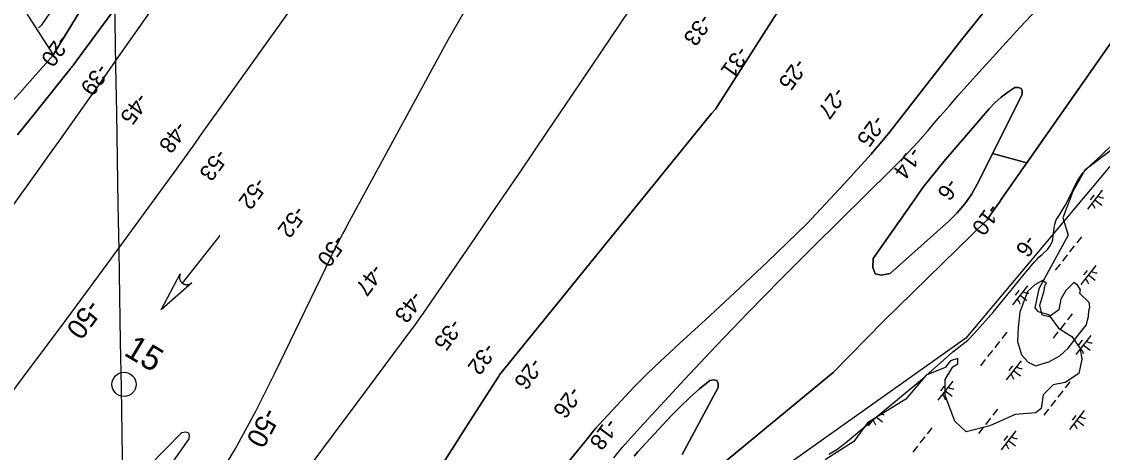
# Model space of a CAD drawing. Extents: x 3896831 to 3918110, y 171006 to 193349.
# Drawn here: x 3904219 to 3906456, y 175459 to 176349 of the extents above; entities that cross this region are included whole.
import ezdxf

# ---------------------------------------------------------------- set-up
doc = ezdxf.new("R2010")
doc.units = 0
for name, color, linetype in [('V-GRID-MAJR', 7, 'Continuous'), ('V-RIVR-EDGE', 7, 'Continuous'), ('V-RIVR-IDEN', 7, 'Continuous'), ('V-RIVR-MILE', 7, 'Continuous'), ('V-RIVR-RANG', 7, 'Continuous'), ('V-RRAP-FSHR', 7, 'Continuous'), ('V-STRM-FLOW', 7, 'Continuous'), ('V-TOPO-DPTH', 7, 'Continuous'), ('V-TOPO-MAJR', 7, 'Continuous'), ('V-TOPO-MAJR-IDEN', 7, 'Continuous'), ('V-TOPO-MINR', 7, 'Continuous'), ('V-TOPO-SHOR', 7, 'Continuous'), ('V-WETL-SWMP', 7, 'Continuous')]:
    doc.layers.add(name, color=color, linetype=linetype)

msp = doc.modelspace()

# ---------------------------------------------------------------- linework, layer by layer
at = {"layer": 'V-GRID-MAJR'}
msp.add_spline([(3904462.5, 173418.2), (3904435.1, 175024.2), (3904332, 181084.3), (3904281.2, 184068.5)], degree=3, dxfattribs=at)
at = {"layer": 'V-RIVR-EDGE'}
msp.add_lwpolyline([(3906485.3, 176092), (3906419.6, 176042), (3906394.6, 175998.2), (3906374.3, 175943.5), (3906385.3, 175907.6), (3906324.3, 175796.6), (3906316.5, 175757.5), (3906322.7, 175749.7), (3906344.6, 175743.5), (3906364.9, 175715.3), (3906393.1, 175698.1), (3906410.3, 175673.1), (3906413.4, 175651.2), (3906407.1, 175621.5), (3906379, 175602.8), (3906354, 175598.1), (3906333.7, 175577.8), (3906329, 175549.6), (3906318, 175540.3), (3906275.8, 175537.1), (3906222.7, 175513.7), (3906174.2, 175501.2), (3906150.8, 175523.1), (3906130.5, 175576.2), (3906130.5, 175609), (3906146.1, 175635.6), (3906157, 175641.9), (3906157, 175652.8), (3906141.4, 175648.1), (3906130.5, 175634), (3906091.4, 175618.4), (3906049.2, 175568.4), (3905969.5, 175519.9), (3905941.3, 175480.9), (3905881.9, 175443.3)], dxfattribs=at)
at = {"layer": 'V-RIVR-MILE'}
msp.add_circle((3904430.9, 175599.1), 25, dxfattribs=at)
at = {"layer": 'V-RRAP-FSHR'}
msp.add_lwpolyline([(3908001.4, 176472.2), (3907201.3, 176920.5), (3906173.6, 175695), (3905294, 175071.7), (3904787.4, 174237.7)], dxfattribs=at)
at = {"layer": 'V-STRM-FLOW'}
msp.add_line((3904629.1, 175906.9), (3904551.5, 175808.6), dxfattribs=at)
msp.add_lwpolyline([(3904571, 175809.1), (3904507.6, 175753), (3904547.4, 175827.7), (3904546.8, 175826.3), (3904546.3, 175824.9), (3904546.2, 175824.4), (3904546, 175823.9), (3904545.9, 175823.2), (3904545.8, 175822.6), (3904545.8, 175822.1), (3904545.7, 175821.4), (3904545.7, 175820.6), (3904545.7, 175820.2), (3904545.7, 175819.6), (3904545.8, 175818.9), (3904545.8, 175818.3), (3904545.9, 175817.7), (3904546, 175817.3), (3904546.1, 175816.9), (3904546.3, 175816.4), (3904546.4, 175815.9), (3904546.6, 175815.4), (3904546.7, 175815), (3904547, 175814.5), (3904547.2, 175813.9), (3904547.4, 175813.5), (3904547.7, 175813), (3904547.9, 175812.6), (3904548.1, 175812.3), (3904548.3, 175812), (3904548.6, 175811.6), (3904548.9, 175811.2), (3904549.2, 175810.8), (3904549.6, 175810.4), (3904549.9, 175810.1), (3904550.2, 175809.7), (3904550.5, 175809.4), (3904551, 175809), (3904551.5, 175808.6), (3904551.6, 175808.5), (3904551.9, 175808.3), (3904552.2, 175808.1), (3904552.5, 175807.9), (3904552.8, 175807.7), (3904553.1, 175807.5), (3904553.4, 175807.3), (3904553.6, 175807.2), (3904554, 175807), (3904554.3, 175806.8), (3904554.6, 175806.7), (3904555.2, 175806.4), (3904555.5, 175806.3), (3904555.8, 175806.2), (3904556.1, 175806.1), (3904556.5, 175806), (3904556.9, 175805.9), (3904557.3, 175805.8), (3904557.7, 175805.7), (3904558, 175805.6), (3904558.3, 175805.5), (3904558.7, 175805.5), (3904559, 175805.4), (3904559.4, 175805.4), (3904559.8, 175805.4), (3904560.2, 175805.3), (3904560.7, 175805.3), (3904561.1, 175805.3), (3904561.5, 175805.3), (3904561.9, 175805.4), (3904562.2, 175805.4), (3904562.6, 175805.4), (3904563.1, 175805.5), (3904563.1, 175805.5), (3904563.4, 175805.5), (3904563.7, 175805.6), (3904564, 175805.6), (3904564.4, 175805.7), (3904564.7, 175805.8), (3904565, 175805.9), (3904565.4, 175806), (3904565.8, 175806.1), (3904566, 175806.2), (3904566.4, 175806.3), (3904566.8, 175806.5), (3904567.1, 175806.6), (3904567.3, 175806.7), (3904567.5, 175806.8), (3904567.7, 175806.9), (3904568, 175807.1), (3904568.3, 175807.2), (3904568.6, 175807.4), (3904568.8, 175807.5), (3904569.2, 175807.8), (3904569.4, 175807.9), (3904569.7, 175808.1), (3904570.1, 175808.4), (3904570.4, 175808.6), (3904570.6, 175808.8), (3904570.8, 175808.9), (3904570.9, 175809)], close=True, dxfattribs=at)
at = {"layer": 'V-TOPO-DPTH'}
for points in [[(3904799.7, 176900.9), (3904331.9, 176267.3), (3904330.3, 176265.2), (3904328.6, 176263), (3904327, 176260.9), (3904325.3, 176258.7), (3904323.7, 176256.6), (3904322, 176254.4), (3904320.3, 176252.3), (3904318.6, 176250.2), (3904247.5, 176161.7), (3904210.5, 176115.2)], [(3904210.5, 176115.2), (3904247.5, 176161.7), (3904318.6, 176250.2), (3904320.3, 176252.3), (3904322, 176254.4), (3904323.7, 176256.6), (3904325.3, 176258.7), (3904327, 176260.9), (3904328.6, 176263), (3904330.3, 176265.2), (3904331.9, 176267.3), (3904799.7, 176900.9)], [(3904426.4, 174510.2), (3904808.6, 174976.7), (3904809.5, 174976.7), (3904811.1, 174977.5), (3904811.8, 174978.3), (3905022.7, 175325.1), (3905053.3, 175375), (3905084.1, 175424.7), (3905115.4, 175474.1), (3905147, 175523.4), (3905207, 175616.4), (3905208.1, 175619.1), (3905647, 176159.4), (3905655.1, 176168.1), (3905914, 176573.8), (3905940.5, 176609.6), (3905968.3, 176644.2), (3905998, 176677.2), (3906029, 176709.2), (3906062.2, 176738.6), (3906096.9, 176765.8), (3906134, 176789.7), (3906172.7, 176811.4), (3906272.9, 176861.8)], [(3906272.9, 176861.8), (3906172.7, 176811.4), (3906134, 176789.7), (3906096.9, 176765.8), (3906062.2, 176738.6), (3906029, 176709.2), (3905998, 176677.2), (3905968.3, 176644.2), (3905940.5, 176609.6), (3905914, 176573.8), (3905655.1, 176168.1), (3905647, 176159.4), (3905208.1, 175619.1), (3905207, 175616.4), (3905147, 175523.4), (3905115.4, 175474.1), (3905084.1, 175424.7), (3905053.3, 175375), (3905022.7, 175325.1), (3904811.8, 174978.3), (3904811.1, 174977.5), (3904809.5, 174976.7), (3904808.6, 174976.7), (3904426.4, 174510.2)], [(3906657.1, 176567.6), (3906656.4, 176566.7), (3906299.5, 176057)], [(3903989.7, 175948.1), (3904284.6, 176280.7), (3904284.8, 176281), (3904284.9, 176281.2), (3904423.5, 176509)], [(3904423.5, 176509), (3904284.9, 176281.2), (3904284.8, 176281), (3904284.6, 176280.7)], [(3904820.2, 175436.4), (3904864.8, 175495.8), (3904909.2, 175555.2), (3904953.6, 175614.6), (3905023.5, 175708.5), (3905032.8, 175721.1), (3905042, 175733.8), (3905051, 175746.6), (3905059.9, 175759.5), (3905148, 175888), (3905200.8, 175965.2), (3905253.5, 176042.5), (3905306, 176120), (3905358.5, 176197.5), (3905477, 176373.3)], [(3904820.2, 175436.4), (3904864.8, 175495.8), (3904909.2, 175555.2), (3904953.6, 175614.6), (3905023.5, 175708.5), (3905032.8, 175721.1), (3905042, 175733.8), (3905051, 175746.6), (3905059.9, 175759.5), (3905148, 175888), (3905200.8, 175965.2), (3905253.5, 176042.5), (3905306, 176120), (3905358.5, 176197.5), (3905477, 176373.3)], [(3905302.6, 175379.7), (3905393.4, 175491.5), (3905400.5, 175500.1), (3905407.7, 175508.5), (3905415, 175516.8), (3905422.5, 175525.1), (3905459.9, 175565.4), (3905486.4, 175593.3), (3905513.5, 175620.8), (3905541.3, 175647.5), (3905569.6, 175673.7), (3905573.4, 175677.1), (3905603.9, 175704.8), (3905634.2, 175732.5), (3905664.4, 175760.4), (3905694.5, 175788.5), (3905762.9, 175852.5), (3905803.7, 175891.7), (3905843.9, 175931.5), (3905883, 175972.3), (3905921.4, 176013.8), (3905977.3, 176075.5), (3905987.2, 176086.7), (3905997, 176098), (3906006.5, 176109.6), (3906015.8, 176121.3), (3906164.7, 176311.6), (3906218.2, 176378.2)], [(3906218.2, 176378.2), (3906164.7, 176311.6), (3906015.8, 176121.3), (3906006.5, 176109.6), (3905997, 176098), (3905987.2, 176086.7), (3905977.3, 176075.5), (3905921.4, 176013.8), (3905883, 175972.3), (3905843.9, 175931.5), (3905803.7, 175891.7), (3905762.9, 175852.5), (3905694.5, 175788.5), (3905664.4, 175760.4), (3905634.2, 175732.5), (3905603.9, 175704.8), (3905573.4, 175677.1), (3905569.6, 175673.7), (3905541.3, 175647.5), (3905513.5, 175620.8), (3905486.4, 175593.3), (3905459.9, 175565.4), (3905422.5, 175525.1), (3905415, 175516.8), (3905407.7, 175508.5), (3905400.5, 175500.1), (3905393.4, 175491.5), (3905302.6, 175379.7)], [(3904483.2, 176367.5), (3904461.6, 176337.2), (3904440.2, 176306.8), (3904418.9, 176276.2), (3904383.2, 176225), (3904379.8, 176220.1), (3904376.3, 176215.2), (3904372.8, 176210.2), (3904369.4, 176205.3), (3904336.2, 176158.8), (3904316.1, 176130.6), (3904296, 176102.4), (3904275.8, 176074.3), (3904255.6, 176046.2), (3903945, 175614.1)], [(3904483.2, 176367.5), (3904461.6, 176337.2), (3904440.2, 176306.8), (3904418.9, 176276.2), (3904383.2, 176225), (3904379.8, 176220.1), (3904376.3, 176215.2), (3904372.8, 176210.2), (3904369.4, 176205.3), (3904336.2, 176158.8), (3904316.1, 176130.6), (3904296, 176102.4), (3904275.8, 176074.3), (3904255.6, 176046.2), (3903945, 175614.1)], [(3904284.6, 176280.7), (3904227.6, 176369.7)], [(3906299.5, 176057), (3906228.7, 176076.6), (3906289.8, 176198.7), (3906289.8, 176206.1), (3906287.6, 176211.2), (3906282.4, 176213.1), (3906275, 176212.8), (3906260.3, 176203.3), (3906246.4, 176193), (3906233.6, 176181.3), (3906221.5, 176168.7), (3906127.9, 176060.3), (3906113, 176042.5), (3906098.5, 176024.5)], [(3906098.5, 176024.5), (3906084.6, 176006), (3906071.1, 175987.2), (3905981.8, 175859.3), (3905980.8, 175840.6), (3905985.5, 175828.1), (3905998.4, 175825), (3906016.9, 175828.2), (3906138.3, 175936.7), (3906155.5, 175953.9), (3906171.3, 175972.2), (3906184.8, 175992.1), (3906196.9, 176013.2), (3906224.8, 176069), (3906228.7, 176076.6), (3906299.5, 176057), (3906289.4, 176042.6)], [(3906289.4, 176042.6), (3906247.9, 175983.4), (3906242.8, 175976), (3906237.6, 175968.6), (3906232.4, 175961.2), (3906227.3, 175953.8), (3906217.5, 175939.7), (3906216.3, 175938.3), (3906003.2, 175730), (3905898.6, 175623.6), (3905669.4, 175435), (3905578.6, 175357.7), (3905461.5, 175228.7)], [(3905586.1, 175454.5), (3905660.6, 175592.7), (3905660.4, 175601.2), (3905657.9, 175606.9), (3905651.8, 175608.4), (3905643.4, 175607.2), (3905622.4, 175590), (3905602, 175572.2), (3905582.4, 175553.4), (3905563.5, 175534), (3905502.9, 175468.7), (3905494.7, 175459.7), (3905486.7, 175450.5)]]:
    msp.add_lwpolyline(points, dxfattribs=at)
at = {"layer": 'V-TOPO-MAJR'}
for points in [[(3904895.3, 176543.5), (3904588.8, 176113.9), (3904576.5, 176096.6), (3904564.1, 176079.4), (3904551.6, 176062.2), (3904539.2, 176045), (3904403, 175858.3), (3904351.2, 175787.6), (3904299, 175717.1), (3904246.5, 175647), (3904193.6, 175577.1)], [(3904614.7, 175388.6), (3904660.6, 175465.4), (3904703.4, 175544.1), (3904744, 175623.9), (3904858.4, 175860.4), (3904859.5, 175862.7), (3904860.5, 175864.9), (3904861.6, 175867.2), (3904862.7, 175869.5), (3904865, 175874.4), (3904867.3, 175879.2), (3904869.6, 175883.9), (3904872, 175888.5), (3904874.5, 175893.2), (3904878.9, 175901.5), (3904883.7, 175910.2), (3904888.4, 175919), (3904893.1, 175927.7), (3904897.9, 175936.5), (3905072.7, 176258.6), (3905102.8, 176312.9), (3905133.5, 176366.8)], [(3904195, 175054.4), (3904230.5, 175105.2), (3904266.3, 175155.8), (3904319.8, 175230.2), (3904329.3, 175243.3), (3904339, 175256.2), (3904348.9, 175269), (3904358.9, 175281.7), (3904420, 175357.6), (3904451, 175394.5), (3904483, 175430.6), (3904516.4, 175465.4), (3904550.8, 175499.4), (3904558.4, 175500.8), (3904563.7, 175499.7), (3904565.6, 175494.6), (3904565.3, 175486.8), (3904427.1, 175290.3), (3904404.5, 175257.8), (3904382.1, 175225.2), (3904359.9, 175192.4), (3904338, 175159.5), (3904165.8, 174898.4)]]:
    msp.add_lwpolyline(points, dxfattribs=at)
at = {"layer": 'V-TOPO-MINR'}
for points in [[(3904799.7, 176900.9), (3904331.9, 176267.3), (3904330.3, 176265.2), (3904328.6, 176263), (3904327, 176260.9), (3904325.3, 176258.7), (3904323.7, 176256.6), (3904322, 176254.4), (3904320.3, 176252.3), (3904318.6, 176250.2), (3904247.5, 176161.7), (3904210.5, 176115.2)], [(3904426.4, 174510.2), (3904808.6, 174976.7), (3904809.5, 174976.7), (3904811.1, 174977.5), (3904811.8, 174978.3), (3905022.7, 175325.1), (3905053.3, 175375), (3905084.1, 175424.7), (3905115.4, 175474.1), (3905147, 175523.4), (3905207, 175616.4), (3905208.1, 175619.1), (3905647, 176159.4), (3905655.1, 176168.1), (3905914, 176573.8), (3905940.5, 176609.6), (3905968.3, 176644.2), (3905998, 176677.2), (3906029, 176709.2), (3906062.2, 176738.6), (3906096.9, 176765.8), (3906134, 176789.7), (3906172.7, 176811.4), (3906272.9, 176861.8)], [(3904753.3, 174263.4), (3905047.5, 174772.5), (3905578.6, 175357.7), (3905669.4, 175435), (3905898.6, 175623.6), (3906003.2, 175730), (3906216.3, 175938.3), (3906217.5, 175939.7), (3906227.3, 175953.8), (3906232.4, 175961.2), (3906237.6, 175968.6), (3906242.8, 175976), (3906247.9, 175983.4), (3906656.4, 176566.7), (3906657.1, 176567.6)], [(3904423.5, 176509), (3904284.9, 176281.2), (3904284.8, 176281), (3904284.6, 176280.7), (3903989.7, 175948.1)], [(3904328.4, 176442.9), (3904260.6, 176343.1), (3904259.2, 176341.2), (3904255.8, 176337.8), (3904253.9, 176336.3)], [(3904820.2, 175436.4), (3904864.8, 175495.8), (3904909.2, 175555.2), (3904953.6, 175614.6), (3905023.5, 175708.5), (3905032.8, 175721.1), (3905042, 175733.8), (3905051, 175746.6), (3905059.9, 175759.5), (3905148, 175888), (3905200.8, 175965.2), (3905253.5, 176042.5), (3905306, 176120), (3905358.5, 176197.5), (3905477, 176373.3)], [(3905302.6, 175379.7), (3905393.4, 175491.5), (3905400.5, 175500.1), (3905407.7, 175508.5), (3905415, 175516.8), (3905422.5, 175525.1), (3905459.9, 175565.4), (3905486.4, 175593.3), (3905513.5, 175620.8), (3905541.3, 175647.5), (3905569.6, 175673.7), (3905573.4, 175677.1), (3905603.9, 175704.8), (3905634.2, 175732.5), (3905664.4, 175760.4), (3905694.5, 175788.5), (3905762.9, 175852.5), (3905803.7, 175891.7), (3905843.9, 175931.5), (3905883, 175972.3), (3905921.4, 176013.8), (3905977.3, 176075.5), (3905987.2, 176086.7), (3905997, 176098), (3906006.5, 176109.6), (3906015.8, 176121.3), (3906164.7, 176311.6), (3906218.2, 176378.2)], [(3905444.6, 175447), (3905462.2, 175468.4), (3905480.4, 175489.3), (3905499, 175509.9), (3905591.2, 175609.2), (3905656.6, 175678.8), (3905722.7, 175747.7), (3905789.6, 175815.8), (3905857.2, 175883.3), (3906019.7, 176043.6), (3906030.7, 176054.6), (3906041.7, 176065.7), (3906052.5, 176077), (3906063.1, 176088.4), (3906073.7, 176099.9), (3906084.1, 176111.5), (3906094.4, 176123.2), (3906104.6, 176135), (3906120.4, 176153.7), (3906138.6, 176174.8), (3906156.9, 176195.8), (3906175.4, 176216.6), (3906194.1, 176237.2), (3906285.2, 176336.9), (3906333.7, 176388.5)], [(3904483.2, 176367.5), (3904461.6, 176337.2), (3904440.2, 176306.8), (3904418.9, 176276.2), (3904383.2, 176225), (3904379.8, 176220.1), (3904376.3, 176215.2), (3904372.8, 176210.2), (3904369.4, 176205.3), (3904336.2, 176158.8), (3904316.1, 176130.6), (3904296, 176102.4), (3904275.8, 176074.3), (3904255.6, 176046.2), (3903945, 175614.1)], [(3906098.5, 176024.5), (3906113, 176042.5), (3906127.9, 176060.3), (3906221.5, 176168.7), (3906233.6, 176181.3), (3906246.4, 176193), (3906260.3, 176203.3), (3906275, 176212.8), (3906282.4, 176213.1), (3906287.6, 176211.2), (3906289.8, 176206.1), (3906289.8, 176198.7), (3906196.9, 176013.2), (3906184.8, 175992.1), (3906171.3, 175972.2), (3906155.5, 175953.9), (3906138.3, 175936.7), (3906016.9, 175828.2), (3905998.4, 175825), (3905985.5, 175828.1), (3905980.8, 175840.6), (3905981.8, 175859.3), (3906071.1, 175987.2), (3906084.6, 176006), (3906098.5, 176024.5)], [(3905486.7, 175450.5), (3905494.7, 175459.7), (3905502.9, 175468.7), (3905563.5, 175534), (3905582.4, 175553.4), (3905602, 175572.2), (3905622.4, 175590), (3905643.4, 175607.2), (3905651.8, 175608.4), (3905657.9, 175606.9), (3905660.4, 175601.2), (3905660.6, 175592.7), (3905586.1, 175454.5)]]:
    msp.add_lwpolyline(points, dxfattribs=at)
at = {"layer": 'V-TOPO-SHOR'}
msp.add_lwpolyline([(3906384.9, 175674.3), (3906405.6, 175700.8), (3906422.2, 175721.9), (3906427.2, 175739.3), (3906428.2, 175751.4), (3906429.7, 175758.7), (3906428.5, 175768.2), (3906409.5, 175787.4), (3906411, 175794.7), (3906405.1, 175803.6), (3906397.2, 175809.8), (3906380, 175793.4), (3906370.2, 175775.5), (3906365.7, 175753.4), (3906345.9, 175739), (3906331.2, 175742), (3906326.3, 175762.9), (3906334.9, 175790.3), (3906337.9, 175805), (3906340, 175807.7), (3906332.1, 175813.9), (3906316.4, 175804.8), (3906301.3, 175791), (3906285, 175748.4), (3906281.6, 175716.9), (3906280.3, 175688), (3906288.5, 175660.3), (3906302.3, 175645.2), (3906317.6, 175637.5), (3906345.3, 175645.6), (3906367.7, 175657.9)], close=True, dxfattribs=at)
at = {"layer": 'V-WETL-SWMP'}
for p, q in [((3906452.9, 176071.5), (3906517, 176134.4)), ((3906431.3, 176052.7), (3906452.9, 176071.5)), ((3906410, 176028.2), (3906416.1, 176037.1)), ((3906416.1, 176037.1), (3906424.4, 176045.4)), ((3906424.4, 176045.4), (3906431.3, 176052.7)), ((3906399.5, 176011.1), (3906404.6, 176020.2)), ((3906404.6, 176020.2), (3906410, 176028.2)), ((3906390, 175990.5), (3906395.6, 176002.5)), ((3906395.6, 176002.5), (3906399.5, 176011.1)), ((3906455.8, 176000.7), (3906425, 175961.4)), ((3906378.8, 175969.2), (3906390, 175990.5)), ((3906438, 175990.5), (3906430.6, 175981.1)), ((3906440.4, 175981), (3906454.6, 175969.9)), ((3906360.6, 175939.3), (3906367, 175950)), ((3906367, 175950), (3906371.4, 175957)), ((3906371.4, 175957), (3906378.8, 175969.2)), ((3906356.1, 175922.2), (3906357.8, 175930.8)), ((3906357.8, 175930.8), (3906360.6, 175939.3)), ((3906353.4, 175898.1), (3906354.1, 175906.4)), ((3906354.1, 175906.4), (3906354.6, 175912.4)), ((3906354.6, 175912.4), (3906356.1, 175922.2)), ((3906412.7, 175904.6), (3906402.8, 175892)), ((3906342.7, 175878.1), (3906348, 175885.4)), ((3906348, 175885.4), (3906351.6, 175892.4)), ((3906351.6, 175892.4), (3906353.4, 175898.1)), ((3906397.9, 175885.7), (3906388, 175873.1)), ((3906320.3, 175857.7), (3906324.4, 175862.2)), ((3906324.4, 175862.2), (3906331.8, 175868.4)), ((3906331.8, 175868.4), (3906342.7, 175878.1)), ((3906383.1, 175866.8), (3906373.2, 175854.2)), ((3906291.5, 175823.4), (3906315.4, 175852.3)), ((3906315.4, 175852.3), (3906320.3, 175857.7)), ((3906368.3, 175847.9), (3906358.4, 175835.3)), ((3906442.4, 175845.2), (3906411.6, 175805.8)), ((3906230.9, 175748.9), (3906291.5, 175823.4)), ((3906424.6, 175835), (3906417.2, 175825.5)), ((3906427, 175825.5), (3906441.1, 175814.4)), ((3906301, 175803.2), (3906270.2, 175763.9)), ((3906283.2, 175793), (3906275.8, 175783.6)), ((3906285.6, 175783.5), (3906299.8, 175772.4)), ((3906295.5, 175775.8), (3906299.8, 175772.4)), ((3906191.6, 175704.8), (3906230.9, 175748.9)), ((3906378.9, 175726.5), (3906369.1, 175713.9)), ((3906378.9, 175726.5), (3906369.1, 175713.9)), ((3906393.7, 175745.4), (3906383.9, 175732.8)), ((3906393.7, 175745.4), (3906383.9, 175732.8)), ((3906177.5, 175690.8), (3906191.6, 175704.8)), ((3906257.9, 175707), (3906248, 175694.4)), ((3906364.1, 175707.6), (3906354.2, 175695)), ((3906364.1, 175707.6), (3906354.2, 175695)), ((3906146.6, 175666.5), (3906177.5, 175690.8)), ((3906243.1, 175688.2), (3906233.2, 175675.6)), ((3906431.9, 175700.6), (3906401.1, 175661.2)), ((3906414.1, 175690.4), (3906406.7, 175681)), ((3906416.5, 175680.9), (3906430.7, 175669.8)), ((3906083.5, 175610.6), (3906146.6, 175666.5)), ((3906228.3, 175669.3), (3906218.4, 175656.7)), ((3906213.5, 175650.4), (3906203.6, 175637.8)), ((3906287.6, 175647.6), (3906256.8, 175608.3)), ((3906269.8, 175637.4), (3906262.4, 175628)), ((3906272.2, 175628), (3906286.3, 175616.9)), ((3906004, 175545.3), (3906083.5, 175610.6)), ((3906146.2, 175605.7), (3906115.4, 175566.3)), ((3906128.4, 175595.5), (3906121, 175586.1)), ((3906388.8, 175604.4), (3906378.9, 175591.8)), ((3906130.8, 175586), (3906145, 175574.9)), ((3906374, 175585.5), (3906364.1, 175573)), ((3905924.4, 175478.5), (3906004, 175545.3)), ((3906238.9, 175547.9), (3906229, 175535.3)), ((3906344.4, 175547.8), (3906334.5, 175535.2)), ((3906359.2, 175566.7), (3906349.3, 175554.1)), ((3906418.5, 175545), (3906387.7, 175505.7)), ((3905980.9, 175525.9), (3905971, 175513.4)), ((3905987.9, 175531.9), (3906000.6, 175521.9)), ((3906224.1, 175529), (3906214.2, 175516.4)), ((3906400.7, 175534.8), (3906393.3, 175525.4)), ((3906403.1, 175525.4), (3906417.3, 175514.2)), ((3906103.1, 175509.5), (3906093.2, 175496.9)), ((3906209.3, 175510.1), (3906199.4, 175497.5)), ((3906277.1, 175503.1), (3906246.3, 175463.7)), ((3905906.1, 175464.6), (3905924.4, 175478.5)), ((3906088.3, 175490.6), (3906078.4, 175478)), ((3906259.3, 175492.9), (3906251.9, 175483.4)), ((3906261.7, 175483.4), (3906275.9, 175472.3)), ((3905889.6, 175454.9), (3905906.1, 175464.6)), ((3906073.5, 175471.7), (3906063.6, 175459.2))]:
    msp.add_line(p, q, dxfattribs=at)
msp.add_lwpolyline([(3906384.9, 175674.3), (3906405.6, 175700.8), (3906422.2, 175721.9), (3906427.2, 175739.3), (3906428.2, 175751.4), (3906429.7, 175758.7), (3906428.5, 175768.2), (3906409.5, 175787.4), (3906411, 175794.7), (3906405.1, 175803.6), (3906397.2, 175809.8), (3906380, 175793.4), (3906370.2, 175775.5), (3906365.7, 175753.4), (3906345.9, 175739), (3906331.2, 175742), (3906326.3, 175762.9), (3906334.9, 175790.3), (3906337.9, 175805), (3906340, 175807.7), (3906332.1, 175813.9), (3906316.4, 175804.8), (3906301.3, 175791), (3906285, 175748.4), (3906281.6, 175716.9), (3906280.3, 175688), (3906288.5, 175660.3), (3906302.3, 175645.2), (3906317.6, 175637.5), (3906345.3, 175645.6), (3906367.7, 175657.9)], close=True, dxfattribs=at)
for centre, start, end in [((3906423.5, 175959.2), 11.1403, 52.6839), ((3906457.6, 176002.6), 231.1403, 272.6839), ((3906410.1, 175803.6), 11.1403, 52.6839), ((3906444.2, 175847.1), 231.1403, 272.6839), ((3906302.8, 175805.1), 231.1403, 272.6839), ((3906268.7, 175761.6), 11.1403, 52.6839), ((3906302.8, 175805.1), 261.0162, 272.6839), ((3906433.7, 175702.5), 231.1403, 272.6839), ((3906399.7, 175659), 11.1403, 52.6839), ((3906289.4, 175649.6), 231.1403, 272.6839), ((3906255.3, 175606.1), 11.1403, 52.6839), ((3906148, 175607.6), 231.1403, 272.6839), ((3906113.9, 175564.1), 11.1403, 52.6839), ((3905969.6, 175511.2), 11.1403, 52.6839), ((3906003.7, 175554.6), 244.5452, 272.6839), ((3906420.3, 175546.9), 231.1403, 272.6839), ((3906386.2, 175503.5), 11.1403, 52.6839), ((3906278.9, 175505), 231.1403, 272.6839), ((3906244.9, 175461.5), 11.1403, 52.6839)]:
    msp.add_arc(centre, 17.6, start, end, dxfattribs=at)

# ---------------------------------------------------------------- texts
at = {"layer": 'V-RIVR-IDEN'}
msp.add_text('15', height=50, rotation=329.1417, dxfattribs=at).set_placement((3904428.3, 175661))
at = {"layer": 'V-RIVR-RANG'}
for s, rotation, p in [('-33', 234.1437, (3905625, 176367.8)), ('-20', 233.6993, (3904295.4, 176324.6)), ('-31', 234.1437, (3905702, 176301.2)), ('-25', 233.9983, (3905821.8, 176275.8)), ('-39', 233.6993, (3904377.3, 176265.1)), ('-45', 233.6993, (3904459.3, 176204.6)), ('-27', 233.9983, (3905902.4, 176216.6)), ('-25', 233.9983, (3905983.9, 176158.7)), ('-48', 233.6993, (3904539.6, 176145.9)), ('-14', 233.9983, (3906059.5, 176092.5)), ('-53', 233.6993, (3904623.2, 176088.4)), ('-52', 233.6993, (3904704.2, 176029.5)), ('-6', 233.9983, (3906136.1, 176027.9)), ('-52', 233.6993, (3904785.2, 175970.9)), ('-10', 233.9983, (3906221.9, 175975.8)), ('-50', 233.6993, (3904867.1, 175910.6)), ('-6', 233.9983, (3906298.2, 175910.7)), ('-47', 233.6993, (3904945.4, 175850.8)), ('-43', 233.6993, (3905027.4, 175794.8)), ('-35', 233.6993, (3905108.5, 175737.4)), ('-32', 233.6993, (3905178.5, 175687.5)), ('-26', 233.5583, (3905274.9, 175656.8)), ('-26', 233.5583, (3905355.5, 175597.6)), ('-18', 233.5583, (3905431.2, 175531.8))]:
    msp.add_text(s, height=33.5, rotation=rotation, dxfattribs=at).set_placement(p)
at = {"layer": 'V-TOPO-MAJR-IDEN'}
for rotation, p in [(233.4987, (3904356.8, 175777.8)), (241.4774, (3904720.8, 175554.4))]:
    msp.add_text('-50', height=41.5, rotation=rotation, dxfattribs=at).set_placement(p)

doc.saveas('drawing.dxf')
